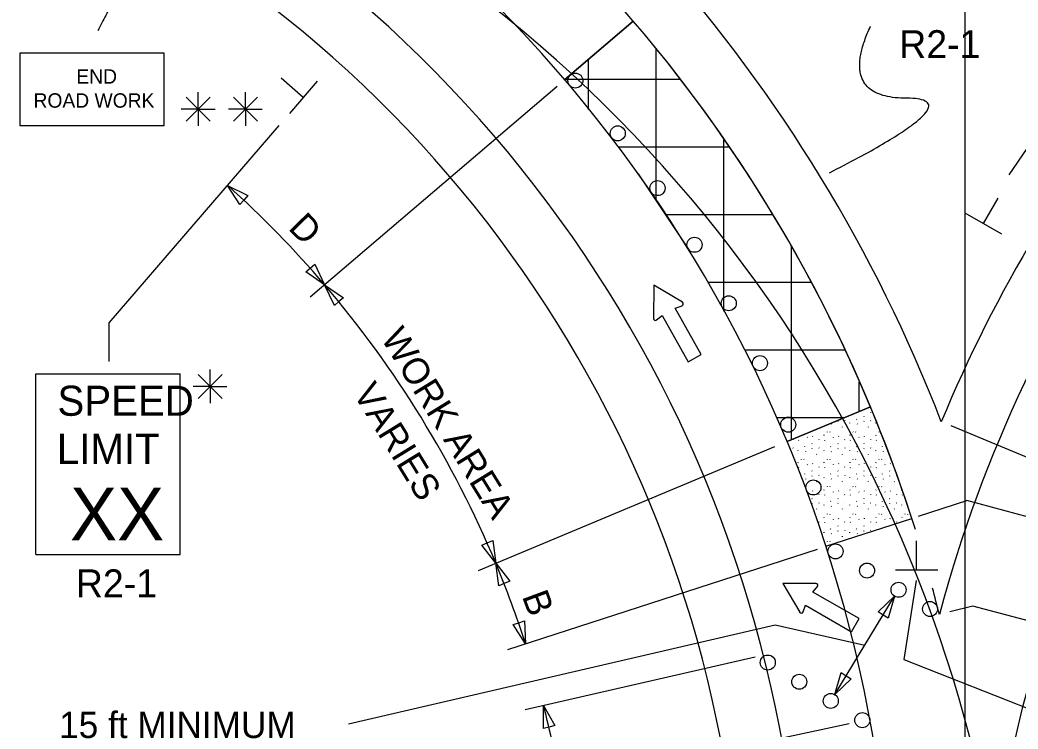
# Model space of a CAD drawing. Extents: x 16729 to 18464, y 5737 to 6974.
# Drawn here: x 16729.4 to 16994.8, y 6633.2 to 6821.9 of the extents above; entities that cross this region are included whole.
import ezdxf

# ---------------------------------------------------------------- set-up
doc = ezdxf.new("R2010")
doc.units = 0
for name, color, linetype in [('ALI_LEGAL_EX', 7, 'Continuous'), ('MT_SCRATCH_LEVEL_A', 7, 'Continuous'), ('PAVT_EDGE_EX', 7, 'Continuous'), ('TRAFFIC_SIGNS_PR', 7, 'Continuous'), ('TYPICAL_TEXT_DIMEN_PR', 7, 'Continuous')]:
    doc.layers.add(name, color=color, linetype=linetype)

msp = doc.modelspace()

# ---------------------------------------------------------------- linework, layer by layer
at = {"layer": 'ALI_LEGAL_EX'}
for p, q in [((16980.68, 6974.12), (16980.68, 6155.98)), ((16980.68, 6891.53), (16980.68, 6027.61))]:
    msp.add_line(p, q, dxfattribs=at)
msp.add_lwpolyline([(16907.75, 6760.19), (16893.85, 6780.96)], dxfattribs=at)
for centre, radius, start, end in [((16597.51, 6569.52), 364, 0, 57.2958), ((16629.65, 6539.64), 364, 0, 57.2958), ((17325.51, 6555.03), 340, 129.5666, 180)]:
    msp.add_arc(centre, radius, start, end, dxfattribs=at)
at = {"layer": 'MT_SCRATCH_LEVEL_A'}
for p, q in [((16892.5, 6821.57), (16874.25, 6805.98)), ((16898.6, 6773.84), (16898.6, 6814.01)), ((16880.6, 6798.05), (16880.6, 6811.4)), ((16874.35, 6806.07), (16904.89, 6806.07)), ((16916.6, 6744.37), (16916.6, 6789.95)), ((16888.59, 6788.07), (16917.91, 6788.07)), ((16901.25, 6770.07), (16929.46, 6770.07)), ((16934.6, 6710.2), (16934.6, 6761.64)), ((16912.34, 6752.07), (16939.69, 6752.07)), ((16922.06, 6734.07), (16948.73, 6734.07)), ((16952.6, 6717.72), (16952.6, 6725.53)), ((16933.43, 6709.72), (16955.58, 6718.96)), ((16955.58, 6718.96), (16933.43, 6709.72)), ((16955.59, 6717.51), (16955.64, 6717.43)), ((16930.55, 6716.07), (16948.65, 6716.07)), ((16945.17, 6714.38), (16945.22, 6714.3)), ((16946.95, 6715.05), (16947, 6715.16)), ((16948.75, 6715.3), (16948.8, 6715.22)), ((16950.03, 6714.72), (16950.04, 6714.6)), ((16951.87, 6715.58), (16951.92, 6715.69)), ((16952.06, 6714.38), (16952.11, 6714.3)), ((16953.8, 6716.44), (16953.85, 6716.37)), ((16953.84, 6715.05), (16953.89, 6715.16)), ((16955.64, 6715.3), (16955.69, 6715.22)), ((16956.92, 6714.72), (16956.93, 6714.6)), ((16943.26, 6711.35), (16943.31, 6711.46)), ((16944.03, 6712.31), (16944.08, 6712.23)), ((16944.76, 6712.28), (16944.81, 6712.2)), ((16948.13, 6713.54), (16948.18, 6713.66)), ((16950.15, 6711.35), (16950.2, 6711.46)), ((16950.91, 6712.31), (16950.97, 6712.23)), ((16951.65, 6712.28), (16951.7, 6712.2)), ((16955.02, 6713.54), (16955.07, 6713.66)), ((16957.04, 6711.35), (16957.09, 6711.46)), ((16957.8, 6712.31), (16957.85, 6712.23)), ((16934.92, 6710.22), (16934.98, 6710.14)), ((16936.45, 6710.08), (16936.51, 6710)), ((16938.74, 6710.9), (16938.8, 6710.82)), ((16940.02, 6709.16), (16940.07, 6709.08)), ((16940.19, 6711.05), (16940.24, 6711.16)), ((16941.81, 6710.22), (16941.86, 6710.14)), ((16943.34, 6710.08), (16943.39, 6710)), ((16945.63, 6710.9), (16945.68, 6710.82)), ((16946.91, 6709.16), (16946.96, 6709.08)), ((16947.08, 6711.05), (16947.13, 6711.16)), ((16948.7, 6710.22), (16948.75, 6710.14)), ((16950.23, 6710.08), (16950.28, 6710)), ((16952.52, 6710.9), (16952.57, 6710.82)), ((16953.8, 6709.16), (16953.85, 6709.08)), ((16953.97, 6711.05), (16954.02, 6711.16)), ((16955.59, 6710.22), (16955.64, 6710.14)), ((16957.12, 6710.08), (16957.17, 6710)), ((16934.97, 6708.01), (16935.02, 6707.93)), ((16936.25, 6707.44), (16936.27, 6707.32)), ((16938.1, 6708.29), (16938.15, 6708.41)), ((16938.28, 6707.09), (16938.34, 6707.01)), ((16940.06, 6707.76), (16940.12, 6707.88)), ((16941.24, 6706.26), (16941.29, 6706.38)), ((16941.86, 6708.01), (16941.91, 6707.93)), ((16943.14, 6707.44), (16943.15, 6707.32)), ((16944.98, 6708.29), (16945.03, 6708.41)), ((16945.17, 6707.09), (16945.22, 6707.01)), ((16946.95, 6707.76), (16947, 6707.88)), ((16948.13, 6706.26), (16948.18, 6706.38)), ((16948.75, 6708.01), (16948.8, 6707.93)), ((16950.03, 6707.44), (16950.04, 6707.32)), ((16951.87, 6708.29), (16951.92, 6708.41)), ((16952.06, 6707.09), (16952.11, 6707.01)), ((16953.84, 6707.76), (16953.89, 6707.88)), ((16955.02, 6706.26), (16955.07, 6706.38)), ((16955.64, 6708.01), (16955.69, 6707.93)), ((16956.92, 6707.44), (16956.93, 6707.32)), ((16958.76, 6708.29), (16958.81, 6708.41)), ((16958.95, 6707.09), (16959, 6707.01)), ((16936.37, 6704.06), (16936.43, 6704.18)), ((16937.14, 6705.02), (16937.19, 6704.94)), ((16937.88, 6704.99), (16937.93, 6704.91)), ((16938.74, 6703.61), (16938.8, 6703.53)), ((16940.19, 6703.76), (16940.24, 6703.88)), ((16943.26, 6704.06), (16943.31, 6704.18)), ((16944.03, 6705.02), (16944.08, 6704.94)), ((16944.76, 6704.99), (16944.81, 6704.91)), ((16945.63, 6703.61), (16945.68, 6703.53)), ((16947.08, 6703.76), (16947.13, 6703.88)), ((16950.15, 6704.06), (16950.2, 6704.18)), ((16950.91, 6705.02), (16950.97, 6704.94)), ((16951.65, 6704.99), (16951.7, 6704.91)), ((16952.52, 6703.61), (16952.57, 6703.53)), ((16953.97, 6703.76), (16954.02, 6703.88)), ((16957.04, 6704.06), (16957.09, 6704.18)), ((16957.8, 6705.02), (16957.85, 6704.94)), ((16958.54, 6704.99), (16958.59, 6704.91)), ((16959.41, 6703.61), (16959.46, 6703.53)), ((16960.86, 6703.76), (16960.91, 6703.88)), ((16936.45, 6702.8), (16936.51, 6702.72)), ((16938.1, 6701.01), (16938.15, 6701.12)), ((16940.02, 6701.88), (16940.07, 6701.8)), ((16941.81, 6702.94), (16941.86, 6702.86)), ((16941.86, 6700.73), (16941.91, 6700.65)), ((16943.34, 6702.8), (16943.39, 6702.72)), ((16944.98, 6701.01), (16945.03, 6701.12)), ((16946.91, 6701.88), (16946.96, 6701.8)), ((16948.7, 6702.94), (16948.75, 6702.86)), ((16948.75, 6700.73), (16948.8, 6700.65)), ((16950.23, 6702.8), (16950.28, 6702.72)), ((16951.87, 6701.01), (16951.92, 6701.12)), ((16953.8, 6701.88), (16953.85, 6701.8)), ((16955.59, 6702.94), (16955.64, 6702.86)), ((16955.64, 6700.73), (16955.69, 6700.65)), ((16957.12, 6702.8), (16957.17, 6702.72)), ((16958.76, 6701.01), (16958.81, 6701.12)), ((16960.68, 6701.88), (16960.74, 6701.8)), ((16962.52, 6700.73), (16962.57, 6700.65)), ((16938.28, 6699.81), (16938.34, 6699.73)), ((16940.06, 6700.48), (16940.12, 6700.59)), ((16941.24, 6698.97), (16941.29, 6699.09)), ((16943.14, 6700.15), (16943.15, 6700.03)), ((16945.17, 6699.81), (16945.22, 6699.73)), ((16946.95, 6700.48), (16947, 6700.59)), ((16948.13, 6698.97), (16948.18, 6699.09)), ((16950.03, 6700.15), (16950.04, 6700.03)), ((16952.06, 6699.81), (16952.11, 6699.73)), ((16953.84, 6700.48), (16953.89, 6700.59)), ((16955.02, 6698.97), (16955.07, 6699.09)), ((16956.92, 6700.15), (16956.93, 6700.03)), ((16958.95, 6699.81), (16959, 6699.73)), ((16960.73, 6700.48), (16960.78, 6700.59)), ((16961.9, 6698.97), (16961.96, 6699.09)), ((16938.74, 6696.33), (16938.8, 6696.25)), ((16940.19, 6696.48), (16940.24, 6696.6)), ((16941.81, 6695.65), (16941.86, 6695.57)), ((16943.26, 6696.78), (16943.31, 6696.89)), ((16943.34, 6695.51), (16943.39, 6695.43)), ((16944.03, 6697.74), (16944.08, 6697.66)), ((16944.76, 6697.71), (16944.81, 6697.63)), ((16945.63, 6696.33), (16945.68, 6696.25)), ((16947.08, 6696.48), (16947.13, 6696.6)), ((16948.7, 6695.65), (16948.75, 6695.57)), ((16950.15, 6696.78), (16950.2, 6696.89)), ((16950.23, 6695.51), (16950.28, 6695.43)), ((16950.91, 6697.74), (16950.97, 6697.66)), ((16951.65, 6697.71), (16951.7, 6697.63)), ((16952.52, 6696.33), (16952.57, 6696.25)), ((16953.97, 6696.48), (16954.02, 6696.6)), ((16955.59, 6695.65), (16955.64, 6695.57)), ((16957.04, 6696.78), (16957.09, 6696.89)), ((16957.12, 6695.51), (16957.17, 6695.43)), ((16957.8, 6697.74), (16957.85, 6697.66)), ((16958.54, 6697.71), (16958.59, 6697.63)), ((16959.41, 6696.33), (16959.46, 6696.25)), ((16960.86, 6696.48), (16960.91, 6696.6)), ((16962.47, 6695.65), (16962.53, 6695.57)), ((16963.92, 6696.78), (16963.96, 6696.85)), ((16964, 6695.51), (16964.06, 6695.43)), ((16940.02, 6694.59), (16940.07, 6694.51)), ((16940.06, 6693.19), (16940.12, 6693.31)), ((16941.86, 6693.44), (16941.91, 6693.36)), ((16943.14, 6692.86), (16943.15, 6692.75)), ((16944.98, 6693.72), (16945.03, 6693.84)), ((16946.91, 6694.59), (16946.96, 6694.51)), ((16946.95, 6693.19), (16947, 6693.31)), ((16948.75, 6693.44), (16948.8, 6693.36)), ((16950.03, 6692.86), (16950.04, 6692.75)), ((16951.87, 6693.72), (16951.92, 6693.84)), ((16953.8, 6694.59), (16953.85, 6694.51)), ((16953.84, 6693.19), (16953.89, 6693.31)), ((16955.64, 6693.44), (16955.69, 6693.36)), ((16956.92, 6692.86), (16956.93, 6692.75)), ((16958.76, 6693.72), (16958.81, 6693.84)), ((16960.68, 6694.59), (16960.74, 6694.51)), ((16960.73, 6693.19), (16960.78, 6693.31)), ((16962.52, 6693.44), (16962.57, 6693.36)), ((16963.8, 6692.86), (16963.82, 6692.75)), ((16941.24, 6691.69), (16941.29, 6691.81)), ((16944.03, 6690.45), (16944.08, 6690.37)), ((16944.76, 6690.42), (16944.81, 6690.34)), ((16945.17, 6692.52), (16945.22, 6692.44)), ((16948.13, 6691.69), (16948.18, 6691.81)), ((16950.91, 6690.45), (16950.97, 6690.37)), ((16951.65, 6690.42), (16951.7, 6690.34)), ((16952.06, 6692.52), (16952.11, 6692.44)), ((16955.02, 6691.69), (16955.07, 6691.81)), ((16957.8, 6690.45), (16957.85, 6690.37)), ((16958.54, 6690.42), (16958.59, 6690.34)), ((16958.95, 6692.52), (16959, 6692.44)), ((16961.9, 6691.69), (16961.96, 6691.81)), ((16964.69, 6690.45), (16964.74, 6690.37)), ((16965.42, 6690.42), (16965.48, 6690.34)), ((16941.81, 6688.36), (16941.86, 6688.29)), ((16943.26, 6689.49), (16943.31, 6689.61)), ((16943.34, 6688.23), (16943.39, 6688.15)), ((16943.74, 6681.84), (16966.58, 6689.25)), ((16945.63, 6689.04), (16945.68, 6688.97)), ((16947.08, 6689.19), (16947.13, 6689.31)), ((16948.7, 6688.36), (16948.75, 6688.29)), ((16950.15, 6689.49), (16950.2, 6689.61)), ((16950.23, 6688.23), (16950.28, 6688.15)), ((16952.52, 6689.04), (16952.57, 6688.97)), ((16953.97, 6689.19), (16954.02, 6689.31)), ((16955.59, 6688.36), (16955.64, 6688.29)), ((16957.04, 6689.49), (16957.09, 6689.61)), ((16957.12, 6688.23), (16957.17, 6688.15)), ((16959.41, 6689.04), (16959.46, 6688.97)), ((16960.86, 6689.19), (16960.91, 6689.31)), ((16962.47, 6688.36), (16962.53, 6688.29)), ((16963.92, 6689.49), (16963.98, 6689.61)), ((16943.14, 6685.58), (16943.15, 6685.46)), ((16944.98, 6686.44), (16945.03, 6686.55)), ((16945.17, 6685.24), (16945.22, 6685.16)), ((16946.91, 6687.31), (16946.96, 6687.23)), ((16946.95, 6685.9), (16947, 6686.02)), ((16948.75, 6686.16), (16948.8, 6686.08)), ((16950.03, 6685.58), (16950.04, 6685.46)), ((16951.87, 6686.44), (16951.92, 6686.55)), ((16952.06, 6685.24), (16952.11, 6685.16)), ((16953.8, 6687.31), (16953.85, 6687.23)), ((16953.84, 6685.9), (16953.89, 6686.02)), ((16955.64, 6686.16), (16955.69, 6686.08)), ((16944.03, 6683.17), (16944.08, 6683.09)), ((16944.76, 6683.14), (16944.81, 6683.06)), ((16948.13, 6684.4), (16948.18, 6684.52))]:
    msp.add_line(p, q, dxfattribs=at)
for start, end in [(22.6538, 40.5126), (17.974, 22.6538)]:
    msp.add_arc((16597.51, 6569.52), 388, start, end, dxfattribs=at)
at = {"layer": 'PAVT_EDGE_EX'}
for centre, radius, start, end in [((16597.51, 6569.52), 404, 21.0961, 62.1564), ((16597.51, 6569.52), 388, 17.5132, 62.1564), ((17325.51, 6569.52), 380, 123.7854, 157.5011), ((17325.51, 6569.52), 364, 123.7854, 165.0045), ((16597.51, 6569.52), 340, 0, 62.1564), ((16597.51, 6569.52), 324, 0, 62.1564), ((16597.51, 6569.52), 388, 14.0482, 15.1223)]:
    msp.add_arc(centre, radius, start, end, dxfattribs=at)
at = {"layer": 'TRAFFIC_SIGNS_PR'}
for p, q in [((16733.58, 6727.69), (16771.97, 6727.69)), ((16733.58, 6679.69), (16733.58, 6727.69)), ((16771.97, 6679.69), (16771.97, 6727.69)), ((16733.58, 6679.69), (16771.97, 6679.69))]:
    msp.add_line(p, q, dxfattribs=at)
msp.add_lwpolyline([(16729.36, 6793.78), (16767.76, 6793.78), (16767.76, 6812.98), (16729.36, 6812.98)], close=True, dxfattribs=at)
for centre in [(16877.1, 6805.72), (16888.37, 6791.69), (16898.94, 6777.12), (16908.78, 6762.05), (16917.89, 6746.49), (16926.19, 6730.56), (16933.71, 6714.2), (16940.41, 6697.5), (16946.29, 6680.49), (16954.68, 6675.38), (16963.06, 6670.27), (16971.44, 6665.16), (16928.27, 6650.92), (16936.65, 6645.81), (16945.03, 6640.7), (16953.42, 6635.59), (16953.42, 6635.59)]:
    msp.add_circle(centre, 2, dxfattribs=at)
at = {"layer": 'TYPICAL_TEXT_DIMEN_PR'}
for p, q in [((16992.47, 6780.68), (17029.33, 6834.75)), ((16750.93, 6820.63), (16750.93, 6820.63)), ((16750.93, 6820.63), (16750.93, 6820.63)), ((16874.25, 6805.98), (16892.49, 6821.57)), ((16750.1, 6819.01), (16750.1, 6819.01)), ((16750.1, 6819.01), (16750.1, 6819.01)), ((16804.71, 6801.27), (16798.81, 6806.35)), ((16808.38, 6805.53), (16801.05, 6797.01)), ((16806.58, 6748.16), (16872.22, 6804.24)), ((16776.79, 6798.15), (16776.79, 6802.61)), ((16789.34, 6798.15), (16789.34, 6802.61)), ((16773.6, 6801.34), (16779.97, 6794.97)), ((16779.97, 6801.34), (16773.6, 6794.97)), ((16792.53, 6801.34), (16786.15, 6794.97)), ((16786.16, 6801.34), (16792.53, 6794.97)), ((16776.79, 6798.15), (16772.25, 6798.15)), ((16776.79, 6798.15), (16779.97, 6798.15)), ((16776.79, 6798.15), (16781.26, 6798.15)), ((16776.79, 6798.15), (16776.79, 6793.65)), ((16789.34, 6798.15), (16784.81, 6798.15)), ((16789.34, 6798.15), (16792.53, 6798.15)), ((16789.34, 6798.15), (16793.82, 6798.15)), ((16789.34, 6798.15), (16789.34, 6793.65)), ((16753.06, 6741.26), (16798.27, 6793.78)), ((16787.88, 6772.78), (16784.57, 6777.86)), ((16784.57, 6777.86), (16789.98, 6775.12)), ((16789.98, 6775.12), (16788.93, 6773.95)), ((16788.93, 6773.95), (16787.88, 6772.78)), ((16985.67, 6767.67), (16989.56, 6774.42)), ((16990.54, 6764.86), (16980.8, 6770.49)), ((16806.58, 6755.86), (16807.77, 6756.88)), ((16807.77, 6756.88), (16810.38, 6751.41)), ((16805.38, 6754.84), (16806.58, 6755.86)), ((16810.38, 6751.41), (16805.38, 6754.84)), ((16813, 6745.93), (16810.38, 6751.41)), ((16810.38, 6751.41), (16815.39, 6747.97)), ((16897.96, 6751.32), (16897.9, 6742.44)), ((16905.59, 6746.74), (16897.96, 6751.32)), ((16814.19, 6746.95), (16813, 6745.93)), ((16815.39, 6747.97), (16814.19, 6746.95)), ((16903.68, 6745.22), (16905.5, 6745.85)), ((16898.71, 6742.05), (16900.2, 6743.27)), ((16900.2, 6743.27), (16907.11, 6730.93)), ((16910.59, 6732.88), (16903.68, 6745.22)), ((16753.06, 6731.04), (16753.06, 6741.26)), ((16907.11, 6730.93), (16910.59, 6732.88)), ((16776.76, 6727.57), (16783.14, 6721.2)), ((16783.14, 6727.57), (16776.76, 6721.2)), ((16779.95, 6724.39), (16779.95, 6728.84)), ((16779.95, 6724.39), (16775.42, 6724.39)), ((16779.95, 6724.39), (16783.14, 6724.39)), ((16779.95, 6724.39), (16784.43, 6724.39)), ((16779.95, 6724.39), (16779.95, 6719.89)), ((16933.43, 6709.71), (16955.58, 6718.96)), ((17093.61, 6665.56), (16977.03, 6713.85)), ((16851.29, 6675.44), (16930.17, 6708.36)), ((16968.4, 6689.84), (16981.21, 6693.99)), ((17093.19, 6664), (16981.21, 6693.99)), ((16852.2, 6682.17), (16853.65, 6682.77)), ((16855.91, 6677.36), (16852.2, 6682.17)), ((16853.65, 6682.77), (16855.1, 6683.38)), ((16855.1, 6683.38), (16855.91, 6677.36)), ((16967.87, 6675.48), (16967.87, 6683.27)), ((16859.09, 6654.38), (16941.54, 6681.12)), ((16856.72, 6671.35), (16855.91, 6677.36)), ((16855.91, 6677.36), (16859.62, 6672.56)), ((16973.49, 6675.48), (16962.24, 6675.48)), ((16858.17, 6671.95), (16856.72, 6671.35)), ((16859.62, 6672.56), (16858.17, 6671.95)), ((16941.15, 6671.92), (16932.25, 6671.94)), ((16932.25, 6671.94), (16936.76, 6664.29)), ((16967.78, 6672.77), (16964.45, 6651.69)), ((16940.29, 6669.64), (16941.52, 6671.12)), ((16952.55, 6662.6), (16940.29, 6669.64)), ((16963.06, 6670.27), (16963.06, 6670.27)), ((16937.65, 6664.37), (16938.3, 6666.18)), ((16938.3, 6666.18), (16950.56, 6659.13)), ((16946.08, 6642.4), (16962.02, 6668.56)), ((16957.63, 6664.37), (16962.02, 6668.56)), ((16962.02, 6668.56), (16960.31, 6662.74)), ((16969.74, 6666.21), (16969.74, 6666.2)), ((16958.97, 6663.56), (16957.63, 6664.37)), ((16960.31, 6662.74), (16958.97, 6663.56)), ((16982.82, 6665.93), (16976.66, 6664.39)), ((17086.29, 6638.21), (16982.82, 6665.93)), ((16930.24, 6660.9), (16816.71, 6634.55)), ((16860.54, 6661.01), (16862.04, 6661.49)), ((16863.85, 6655.92), (16860.54, 6661.01)), ((16862.04, 6661.49), (16863.53, 6661.98)), ((16863.53, 6661.98), (16863.85, 6655.92)), ((16954.05, 6655.48), (16930.24, 6660.9)), ((16950.56, 6659.13), (16952.55, 6662.6)), ((16924.96, 6652.39), (16863.76, 6638.33)), ((16964.45, 6651.69), (17046.11, 6619.48)), ((16946.08, 6642.4), (16947.78, 6648.23)), ((16947.78, 6648.23), (16949.13, 6647.41)), ((16950.47, 6646.59), (16946.08, 6642.4)), ((16949.13, 6647.41), (16950.47, 6646.59)), ((16868.58, 6633.38), (16868.64, 6639.45)), ((16868.64, 6639.45), (16871.62, 6634.16)), ((16840.84, 6611.45), (16949.94, 6634.73)), ((16870.1, 6633.77), (16868.58, 6633.38)), ((16871.62, 6634.16), (16870.1, 6633.77))]:
    msp.add_line(p, q, dxfattribs=at)
for centre, radius, start, end in [((16597.51, 6569.52), 280, 40.5126, 48.082), ((16597.51, 6569.52), 280, 22.6539, 40.5126), ((16905.32, 6746.32), 0.494, 289.2925, 59.0295), ((16898.4, 6742.44), 0.494, 179.6812, 309.2202), ((16597.51, 6569.52), 280, 17.974, 22.6539), ((16941.14, 6671.42), 0.494, 320.1573, 89.8942), ((16937.18, 6664.54), 0.494, 210.5459, 340.0849), ((16597.51, 6569.52), 280, 10.0461, 14.4629)]:
    msp.add_arc(centre, radius, start, end, dxfattribs=at)
for points in [[(16755, 6849.79), (16740.54, 6825.17), (16763.75, 6845.02), (16750.1, 6819.01)], [(16944.67, 6781.19), (16983.59, 6801.04), (16946.72, 6801.04), (16955.6, 6820.2)]]:
    msp.add_open_spline(points, degree=2, dxfattribs=at)

# ---------------------------------------------------------------- texts
at = {"layer": 'TRAFFIC_SIGNS_PR'}
for s, height, p in [('R2-1', 7.44, (16963.25, 6811.69)), ('END', 3.831, (16744.36, 6804.91)), ('ROAD WORK', 3.831, (16732.97, 6798.52)), ('SPEED', 8, (16739.34, 6716.56)), ('LIMIT', 8, (16739.18, 6703.76)), ('XX', 14.031, (16742.69, 6683.45)), ('R2-1', 7.44, (16744.25, 6668.26))]:
    msp.add_text(s, height=height, dxfattribs=at).set_placement(p)
at = {"layer": 'TYPICAL_TEXT_DIMEN_PR'}
for s, rotation, p in [('D', 314.2974, (16800.46, 6766.33)), ('WORK AREA', 301.5829, (16825.2, 6737.26)), ('VARIES', 301.5829, (16817.8, 6722.56)), ('B', 290.315, (16862.83, 6668.56))]:
    msp.add_text(s, height=7, rotation=rotation, dxfattribs=at).set_placement(p)
msp.add_text('15 ft MINIMUM', height=7, dxfattribs=at).set_placement((16739.78, 6630.83))

doc.saveas('drawing.dxf')
